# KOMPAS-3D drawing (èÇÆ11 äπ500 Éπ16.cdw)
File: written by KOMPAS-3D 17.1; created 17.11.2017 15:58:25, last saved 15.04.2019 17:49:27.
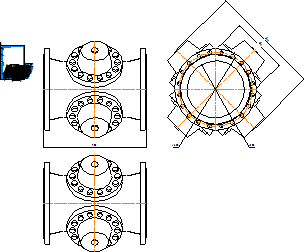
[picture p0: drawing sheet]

Sheet 1: A4, portrait

Title block, sheet 1: name: КАТ11 Ду500 Ру16; material: Внимание! Данный продукт является объектом авторского права ООО «Торговый Дом АДЛ». / Запрещается изменение, копирование, распространение / (в том числе путем копирования на другие сайты и ресурсы в Интернете) / или любое иное использование информации и объектов без предварительного / согласия правообладателя (ООО «Торговый Дом АДЛ»).; mass: 12,4; sheets: 1; organisation: ООО "Торговый дом АДЛ"; sheet format: A4; stored path: \\adlc.lan\data\АДЛ_ПКД\3D-модели\ADL production\Клапаны КАТ ГРАНРЕГ\КАТ11\KOMPAS 2D\КАТ11 Ду500 Ру16.cdw

Views: Вид 1, Проекционный вид 2, Проекционный вид 3
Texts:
  kka
  adl
Dimensions and other numbers on the sheet: 900; 970; 490; 650; 500; 1:1; 1; 12,4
